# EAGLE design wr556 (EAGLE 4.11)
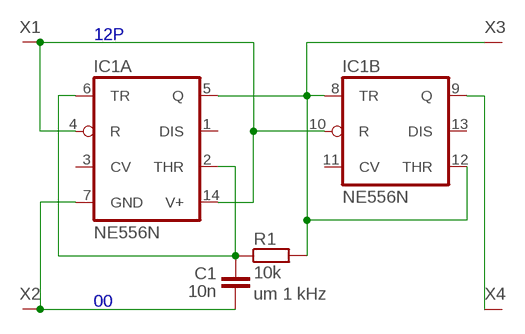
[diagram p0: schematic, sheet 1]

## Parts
C1  10n  C5  [C050-024X044]
IC1  NE556N  [DIL14]
R1  10k  R  [0207/5V]
X1  PAD  [SMD-2MM]
X2  PAD  [SMD-2MM]
X3  PAD  [SMD-2MM]
X4  PAD  [SMD-2MM]

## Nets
00: C1.2 IC1.7(A:GND) X2.1
12P: IC1.4(A:R) IC1.10(B:R) IC1.14(A:V+) X1.1
N$1: IC1.9(B:Q) X4.1
N$4: IC1.5(A:Q) IC1.8(B:TR) IC1.12(B:THR) R1.2 X3.1
N$5: C1.1 IC1.2(A:THR) IC1.6(A:TR) R1.1
Unconnected: IC1.1(A:DIS) IC1.3(A:CV) IC1.11(B:CV) IC1.13(B:DIS)

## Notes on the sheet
- um 1 kHz

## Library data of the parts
C1 = fu:C: Kondensator
IC1 = linear:*556: Dual TIMER
R1 = fu:R: Widerstand
X1-X4 = fu:PAD: Anschlussfeld

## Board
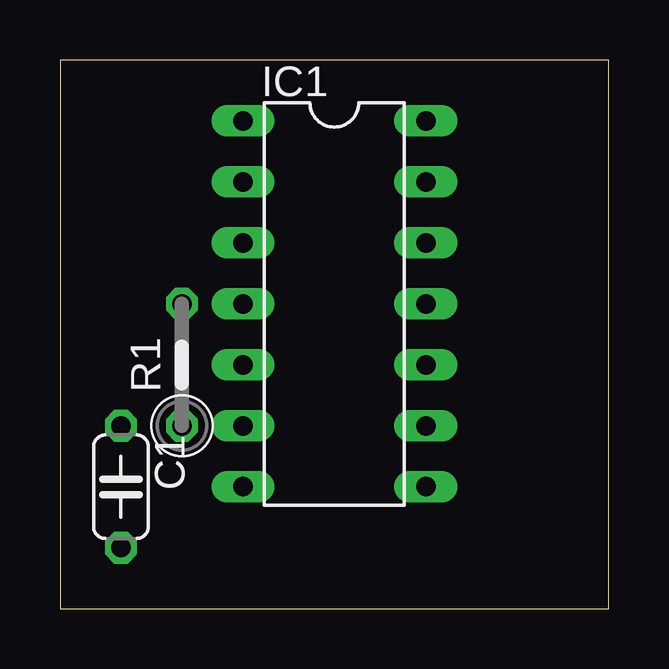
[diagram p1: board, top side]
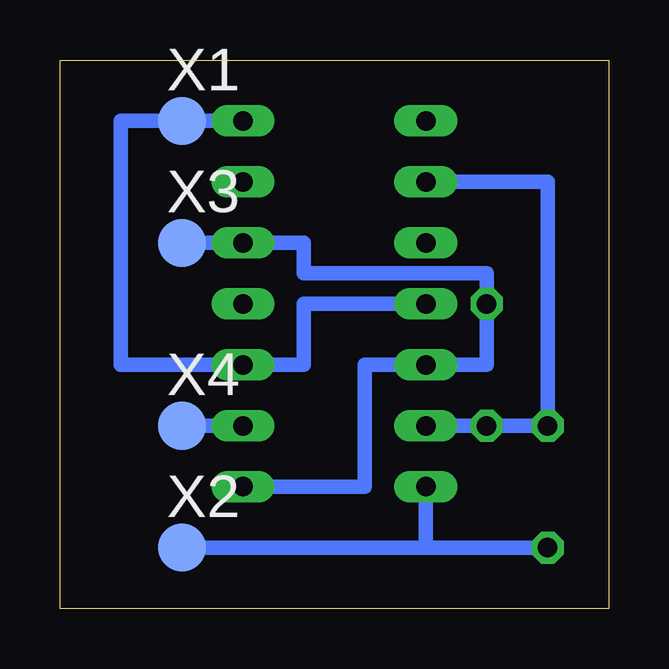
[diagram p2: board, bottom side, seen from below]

Size 22.86 x 22.86 mm. Coordinates in mm from the lower left corner, seen from the top.
Outline: 0,0 22.86,0 22.86,22.86 0,22.86 0,0
Copper layers (1*16): Top 0.035mm / dielectric 1.5mm / Bottom 0.035mm
Design rules "default": minimum track width 10mil, minimum drill 24mil, track to track 8mil, track to pad 8mil, pad to pad 8mil, via to via 8mil, smd to smd 8mil, copper to edge 40mil, drill to drill 8mil, minimum pad ring 10mil, minimum via ring 8mil, stop-mask expansion 4mil, vias tented up to drill 0mil, thermal gap 10mil

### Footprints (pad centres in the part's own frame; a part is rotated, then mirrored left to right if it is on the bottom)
C050-024X044 = drill 0.813 octagon: 1 -2.54,0; 2 2.54,0
DIL14 = drill 0.813 long: 1 -7.62,-3.81; 2 -5.08,-3.81; 3 -2.54,-3.81; 4 0,-3.81; 5 2.54,-3.81; 6 5.08,-3.81; 7 7.62,-3.81; 8 7.62,3.81; 9 5.08,3.81; 10 2.54,3.81; 11 0,3.81; 12 -2.54,3.81; 13 -5.08,3.81; 14 -7.62,3.81
0207/5V = drill 0.813 octagon: 1 -2.54,0; 2 2.54,0
SMD-2MM = smd 2 x 2: 1 0,0

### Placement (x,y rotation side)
C1  2.54,5.08 270 top
IC1  11.43,12.7 270 top
R1  5.08,10.16 90 top
X1  17.78,20.32 0 bottom
X2  17.78,2.54 0 bottom
X3  17.78,15.24 0 bottom
X4  17.78,7.62 0 bottom

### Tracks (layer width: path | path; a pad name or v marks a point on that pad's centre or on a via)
00
  Bottom 0.61: C1.2 7.62,2.54 | 7.62,2.54 X2.1 | 7.62,2.54 IC1.7
12P
  Bottom 0.61: IC1.14 X1.1 20.32,20.32 20.32,10.16 IC1.10 12.7,10.16 12.7,12.7 IC1.4
N$1
  Bottom 0.61: X4.1 IC1.9
N$4
  Bottom 0.61: IC1.12 X3.1 12.7,15.24 12.7,13.97 5.08,13.97 R1.2 5.08,10.16 IC1.5 10.16,10.16 10.16,5.08 IC1.8
N$5
  Bottom 0.61: IC1.6 R1.1 C1.1 2.54,17.78 IC1.2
